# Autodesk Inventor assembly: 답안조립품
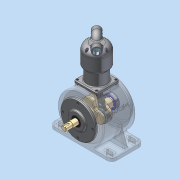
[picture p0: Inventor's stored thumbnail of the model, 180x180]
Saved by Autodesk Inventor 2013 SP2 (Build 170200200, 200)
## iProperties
Created: 2015-06
Part Number: 답안조립품
Document SubType Name: Assembly
Designer: dgall
Author: dgall
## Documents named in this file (15)
- C:\Documents and Settings\dgall\바탕 화면\450605V1003\답안조립품.iam
- C:\Documents and Settings\dgall\바탕 화면\450605V1003\1.본체.ipt
- C:\Documents and Settings\dgall\바탕 화면\450605V1003\메인커버.ipt
- C:\Documents and Settings\dgall\바탕 화면\450605V1003\베어링 6204.ipt
- C:\Documents and Settings\dgall\바탕 화면\450605V1003\오일실.ipt
- C:\Documents and Settings\dgall\바탕 화면\450605V1003\M4x0.7.ipt
- C:\Documents and Settings\dgall\바탕 화면\450605V1003\실린더.ipt
- C:\Documents and Settings\dgall\바탕 화면\450605V1003\실린더헤드.ipt
- C:\Documents and Settings\dgall\바탕 화면\450605V1003\M5x0.8.ipt
- C:\Documents and Settings\dgall\바탕 화면\450605V1003\커넥팅 로드.ipt
- C:\Documents and Settings\dgall\바탕 화면\450605V1003\베어링 NA 4902.ipt
- C:\Documents and Settings\dgall\바탕 화면\450605V1003\크랭크 서브축.ipt
- C:\Documents and Settings\dgall\바탕 화면\450605V1003\메인 크랭크 축-구동부.ipt
- C:\Documents and Settings\dgall\바탕 화면\450605V1003\피스톤.ipt
- C:\Documents and Settings\dgall\바탕 화면\450605V1003\피스톤 핀.ipt
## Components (15 placed, 5 different names)
1. 1.본체:1
2. 피스톤:1
3. 피스톤 핀:1
4. M4x0.7:1
5. M4x0.7:2
6. M4x0.7:3
7. M4x0.7:4
8. M4x0.7:5
9. M4x0.7:6
10. M4x0.7:7
11. M4x0.7:8
12. M5x0.8:1
13. M5x0.8:2
14. M5x0.8:3
15. M5x0.8:4
